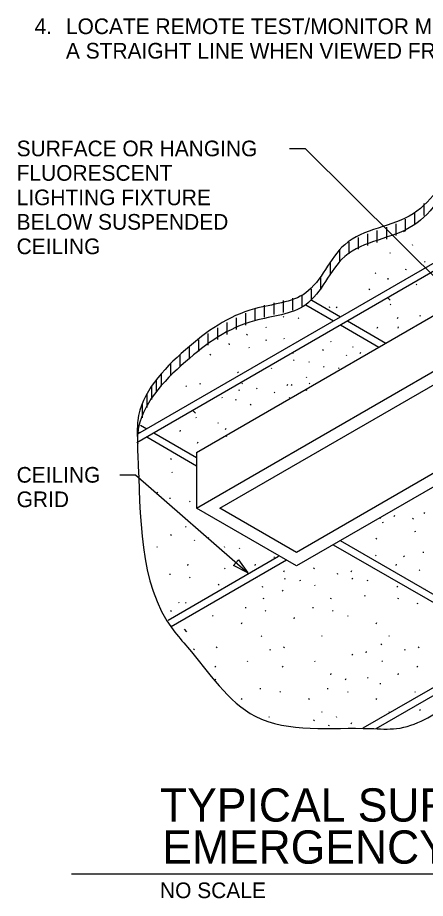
# Model space of a CAD drawing. Extents: x -12092.5 to -12048.3, y -12283.2 to -12205.8.
# Drawn here: x -12092.51 to -12075.14, y -12281.89 to -12244.4 of the extents above; entities that cross this region are included whole.
import ezdxf

# ---------------------------------------------------------------- set-up
doc = ezdxf.new("R2010")
doc.units = 0
for name, color, linetype in [('G-ANNO-TEXT', 7, 'Continuous'), ('G-DETL-LINE', 7, 'Continuous'), ('G-DETL-OTLN', 7, 'Continuous'), ('G-DETL-PATT', 7, 'Continuous')]:
    doc.layers.add(name, color=color, linetype=linetype)

msp = doc.modelspace()

# ---------------------------------------------------------------- linework, layer by layer
at = {"layer": 'G-ANNO-TEXT'}
for p, q in [((-12080.926, -12249.965), (-12080.259, -12249.965)), ((-12080.259, -12249.965), (-12073.795, -12256.39)), ((-12088.159, -12263.859), (-12087.492, -12263.859)), ((-12087.492, -12263.859), (-12082.703, -12268.036)), ((-12090.219, -12280.845), (-12051.694, -12280.845))]:
    msp.add_line(p, q, dxfattribs=at)
msp.add_lwpolyline([(-12083.096, -12267.472), (-12082.703, -12268.036), (-12083.315, -12267.724)], close=True, dxfattribs=at)
at = {"layer": 'G-DETL-LINE'}
for p, q in [((-12064.841, -12249.447), (-12087.432, -12262.49)), ((-12065.21, -12249.313), (-12087.407, -12262.129)), ((-12079.973, -12256.43), (-12078.755, -12257.133)), ((-12080.234, -12256.626), (-12079.055, -12257.307)), ((-12078.455, -12257.307), (-12076.824, -12258.249)), ((-12078.755, -12257.48), (-12077.124, -12258.422)), ((-12054.535, -12261.21), (-12077.813, -12274.649)), ((-12087.272, -12261.748), (-12087.01, -12261.899)), ((-12054.64, -12261.617), (-12077.25, -12274.671)), ((-12087.378, -12262.033), (-12087.31, -12262.072)), ((-12086.71, -12262.072), (-12084.891, -12263.122)), ((-12087.01, -12262.246), (-12084.891, -12263.469)), ((-12078.766, -12266.658), (-12071.369, -12270.929)), ((-12079.067, -12266.832), (-12071.669, -12271.102)), ((-12086.103, -12270.04), (-12081.401, -12267.326)), ((-12081.057, -12267.493), (-12085.964, -12270.325))]:
    msp.add_line(p, q, dxfattribs=at)
for points in [[(-12065.21, -12248.806), (-12068.289, -12248.263), (-12071.882, -12249.46), (-12073.511, -12250.469), (-12075.66, -12252.742), (-12078.578, -12254.061), (-12080.241, -12256.115), (-12082.417, -12256.792), (-12085.365, -12258.54), (-12087.392, -12261.547), (-12087.416, -12262.222)], [(-12065.21, -12249.313), (-12068.289, -12248.77), (-12071.882, -12249.967), (-12073.511, -12250.976), (-12075.66, -12253.249), (-12078.578, -12254.568), (-12080.241, -12256.622), (-12082.417, -12257.299), (-12085.365, -12259.047), (-12087.392, -12262.054), (-12087.392, -12263.005), (-12085.887, -12270.459), (-12085.273, -12271.196), (-12082.387, -12274.137), (-12077.474, -12274.659), (-12076.368, -12274.659), (-12074.064, -12273.585), (-12070.747, -12271.315), (-12067.093, -12270.272), (-12063.192, -12269.382), (-12061.824, -12266.02), (-12056.45, -12263.782), (-12054.538, -12261.235), (-12060.102, -12255.74), (-12060.918, -12251.902), (-12062.515, -12250.552), (-12064.841, -12249.447), (-12065.182, -12249.321)]]:
    msp.add_spline(points, degree=3, dxfattribs=at)
at = {"layer": 'G-DETL-OTLN'}
for p, q in [((-12084.891, -12262.907), (-12068.869, -12253.656)), ((-12084.891, -12265.279), (-12068.869, -12256.029)), ((-12083.891, -12265.279), (-12068.869, -12256.606)), ((-12064.612, -12258.486), (-12080.634, -12267.737)), ((-12065.612, -12258.486), (-12080.634, -12267.159)), ((-12084.891, -12262.907), (-12084.891, -12265.279)), ((-12080.634, -12267.737), (-12084.891, -12265.279)), ((-12080.634, -12267.159), (-12083.891, -12265.279))]:
    msp.add_line(p, q, dxfattribs=at)
at = {"layer": 'G-DETL-PATT'}
for p, q in [((-12075.203, -12252.314), (-12075.203, -12252.821)), ((-12075.603, -12252.695), (-12075.603, -12253.203)), ((-12076.403, -12253.168), (-12076.403, -12253.675)), ((-12076.003, -12252.973), (-12076.003, -12253.48)), ((-12077.203, -12253.457), (-12077.203, -12253.964)), ((-12076.803, -12253.321), (-12076.803, -12253.828)), ((-12076.069, -12253.475), (-12076.047, -12253.508)), ((-12078.403, -12253.949), (-12078.403, -12254.456)), ((-12078.003, -12253.749), (-12078.003, -12254.256)), ((-12077.603, -12253.593), (-12077.603, -12254.1)), ((-12078.803, -12254.256), (-12078.803, -12254.763)), ((-12075.707, -12254.05), (-12075.685, -12254.082)), ((-12076.661, -12254.391), (-12076.639, -12254.423)), ((-12079.203, -12254.805), (-12079.203, -12255.313)), ((-12075.175, -12254.774), (-12075.153, -12254.806)), ((-12077.278, -12255.253), (-12077.257, -12255.285)), ((-12075.977, -12255.136), (-12075.955, -12255.088)), ((-12079.603, -12255.474), (-12079.603, -12255.981)), ((-12076.744, -12255.493), (-12076.739, -12255.541)), ((-12075.53, -12255.736), (-12075.508, -12255.768)), ((-12080.403, -12256.195), (-12080.403, -12256.702)), ((-12080.003, -12255.949), (-12080.003, -12256.456)), ((-12077.536, -12255.983), (-12077.514, -12255.935)), ((-12081.603, -12256.531), (-12081.603, -12257.038)), ((-12081.203, -12256.441), (-12081.203, -12256.948)), ((-12080.803, -12256.339), (-12080.803, -12256.846)), ((-12076.741, -12256.324), (-12076.646, -12256.426)), ((-12082.403, -12256.785), (-12082.403, -12257.292)), ((-12082.003, -12256.636), (-12082.003, -12257.143)), ((-12079.246, -12256.698), (-12079.224, -12256.731)), ((-12078.938, -12256.711), (-12078.917, -12256.743)), ((-12076.637, -12256.587), (-12076.616, -12256.619)), ((-12083.203, -12257.169), (-12083.203, -12257.676)), ((-12082.803, -12256.974), (-12082.803, -12257.481)), ((-12081.197, -12257.114), (-12081.176, -12257.146)), ((-12080.56, -12257.172), (-12080.538, -12257.205)), ((-12076.326, -12257.198), (-12076.304, -12257.15)), ((-12075.364, -12257.111), (-12075.343, -12257.062)), ((-12084.003, -12257.596), (-12084.003, -12258.103)), ((-12083.603, -12257.375), (-12083.603, -12257.882)), ((-12081.943, -12257.556), (-12081.922, -12257.588)), ((-12077.189, -12257.61), (-12077.167, -12257.562)), ((-12076.308, -12257.61), (-12076.286, -12257.562)), ((-12084.403, -12257.837), (-12084.403, -12258.345)), ((-12082.746, -12257.918), (-12082.724, -12257.869)), ((-12081.177, -12258.035), (-12081.156, -12258.067)), ((-12085.203, -12258.407), (-12085.203, -12258.914)), ((-12084.803, -12258.106), (-12084.803, -12258.613)), ((-12083.513, -12258.275), (-12083.507, -12258.323)), ((-12082.667, -12258.418), (-12082.646, -12258.45)), ((-12081.926, -12258.139), (-12081.904, -12258.091)), ((-12079.187, -12258.165), (-12079.165, -12258.198)), ((-12078.25, -12258.389), (-12078.229, -12258.422)), ((-12085.603, -12258.746), (-12085.603, -12259.254)), ((-12084.305, -12258.765), (-12084.283, -12258.716)), ((-12080.784, -12258.689), (-12080.762, -12258.641)), ((-12079.505, -12258.565), (-12079.484, -12258.517)), ((-12078.518, -12258.752), (-12078.496, -12258.785)), ((-12077.914, -12258.689), (-12077.892, -12258.641)), ((-12086.003, -12259.12), (-12086.003, -12259.639)), ((-12080.758, -12258.964), (-12080.736, -12258.996)), ((-12080.11, -12259.034), (-12080.088, -12259.067)), ((-12086.403, -12259.551), (-12086.403, -12260.089)), ((-12083.145, -12259.48), (-12083.123, -12259.513)), ((-12081.712, -12259.305), (-12081.691, -12259.337)), ((-12079.48, -12259.246), (-12079.458, -12259.279)), ((-12078.842, -12259.305), (-12078.821, -12259.337)), ((-12086.603, -12259.798), (-12086.603, -12260.35)), ((-12083.446, -12259.841), (-12083.441, -12259.832)), ((-12080.226, -12259.688), (-12080.204, -12259.72)), ((-12086.803, -12260.079), (-12086.803, -12260.646)), ((-12085.345, -12260.067), (-12085.324, -12260.1)), ((-12084.742, -12260.004), (-12084.72, -12259.956)), ((-12083.078, -12260.271), (-12083.056, -12260.223)), ((-12082.959, -12259.955), (-12082.938, -12259.987)), ((-12082.329, -12260.167), (-12082.308, -12260.199)), ((-12081.028, -12260.05), (-12081.007, -12260.001)), ((-12080.838, -12260.06), (-12080.816, -12260.011)), ((-12080.208, -12260.271), (-12080.187, -12260.223)), ((-12080.089, -12259.955), (-12080.068, -12259.987)), ((-12087.003, -12260.411), (-12087.003, -12260.995)), ((-12083.819, -12260.55), (-12083.798, -12260.582)), ((-12083.217, -12260.685), (-12083.195, -12260.637)), ((-12081.579, -12260.338), (-12081.558, -12260.37)), ((-12080.95, -12260.55), (-12080.928, -12260.582)), ((-12087.203, -12260.841), (-12087.203, -12261.435)), ((-12082.587, -12260.897), (-12082.565, -12260.848)), ((-12085.03, -12261.138), (-12084.935, -12261.239)), ((-12084.927, -12261.401), (-12084.905, -12261.433)), ((-12087.403, -12261.626), (-12087.403, -12262.106)), ((-12083.99, -12261.625), (-12083.968, -12261.657)), ((-12085.588, -12262.012), (-12085.567, -12261.964)), ((-12083.654, -12261.925), (-12083.632, -12261.876)), ((-12083.628, -12262.199), (-12083.606, -12262.232)), ((-12087.39, -12262.517), (-12087.389, -12262.529)), ((-12084.845, -12262.507), (-12084.823, -12262.458)), ((-12085.982, -12263.206), (-12085.96, -12263.158)), ((-12085.948, -12263.734), (-12085.927, -12263.766)), ((-12086.566, -12264.596), (-12086.544, -12264.629)), ((-12086.032, -12264.836), (-12086.026, -12264.885)), ((-12085.186, -12264.979), (-12085.164, -12265.012)), ((-12075.193, -12265.504), (-12075.171, -12265.456)), ((-12077.075, -12265.692), (-12077.053, -12265.724)), ((-12076.975, -12265.866), (-12076.954, -12265.899)), ((-12076.471, -12265.629), (-12076.45, -12265.58)), ((-12075.674, -12265.75), (-12075.652, -12265.701)), ((-12085.356, -12266.054), (-12085.334, -12266.087)), ((-12075.596, -12266.249), (-12075.574, -12266.282)), ((-12085.982, -12266.442), (-12085.96, -12266.393)), ((-12084.994, -12266.629), (-12084.973, -12266.661)), ((-12084.39, -12266.566), (-12084.369, -12266.517)), ((-12077.233, -12266.597), (-12077.211, -12266.548)), ((-12086.586, -12266.911), (-12086.564, -12266.943)), ((-12083.716, -12266.911), (-12083.694, -12266.943)), ((-12083.078, -12266.969), (-12083.057, -12267.002)), ((-12081.592, -12267.353), (-12081.571, -12267.385)), ((-12077.267, -12267.277), (-12077.245, -12267.31)), ((-12076.073, -12267.312), (-12076.051, -12267.344)), ((-12075.242, -12267.134), (-12075.237, -12267.183)), ((-12085.264, -12267.715), (-12085.243, -12267.666)), ((-12082.394, -12267.715), (-12082.373, -12267.666)), ((-12079.891, -12267.863), (-12079.869, -12267.814)), ((-12076.391, -12267.712), (-12076.37, -12267.663)), ((-12086.032, -12268.072), (-12086.026, -12268.12)), ((-12083.696, -12267.832), (-12083.674, -12267.864)), ((-12081.169, -12267.987), (-12081.148, -12267.938)), ((-12078.903, -12268.05), (-12078.882, -12268.082)), ((-12078.3, -12267.987), (-12078.278, -12267.938)), ((-12075.404, -12267.899), (-12075.382, -12267.931)), ((-12085.186, -12268.215), (-12085.164, -12268.247)), ((-12083.953, -12268.562), (-12083.932, -12268.513)), ((-12082.316, -12268.215), (-12082.314, -12268.218)), ((-12081.144, -12268.262), (-12081.122, -12268.294)), ((-12080.495, -12268.332), (-12080.474, -12268.365)), ((-12079.865, -12268.544), (-12079.844, -12268.576)), ((-12078.274, -12268.262), (-12078.252, -12268.294)), ((-12077.625, -12268.332), (-12077.604, -12268.365)), ((-12082.098, -12268.602), (-12082.076, -12268.635)), ((-12081.241, -12268.774), (-12081.219, -12268.806)), ((-12076.358, -12268.602), (-12076.336, -12268.635)), ((-12075.186, -12268.726), (-12075.171, -12268.691)), ((-12085.663, -12269.277), (-12085.642, -12269.31)), ((-12085.356, -12269.29), (-12085.334, -12269.322)), ((-12082.043, -12269.136), (-12082.022, -12269.088)), ((-12079.174, -12269.136), (-12079.152, -12269.088)), ((-12077.742, -12268.986), (-12077.72, -12269.018)), ((-12076.304, -12269.136), (-12076.282, -12269.088)), ((-12075.484, -12269.357), (-12075.462, -12269.309)), ((-12085.982, -12269.677), (-12085.96, -12269.629)), ((-12082.811, -12269.493), (-12082.805, -12269.541)), ((-12081.965, -12269.636), (-12081.943, -12269.668)), ((-12079.941, -12269.493), (-12079.935, -12269.541)), ((-12079.095, -12269.636), (-12079.073, -12269.668)), ((-12084.205, -12269.848), (-12084.183, -12269.88)), ((-12080.732, -12269.983), (-12080.711, -12269.935)), ((-12078.465, -12269.848), (-12078.444, -12269.88)), ((-12085.416, -12270.436), (-12085.321, -12270.537)), ((-12082.973, -12270.195), (-12082.951, -12270.146)), ((-12077.233, -12270.195), (-12077.211, -12270.146)), ((-12082.135, -12270.711), (-12082.114, -12270.743)), ((-12079.573, -12270.698), (-12079.551, -12270.731)), ((-12076.703, -12270.698), (-12076.681, -12270.731)), ((-12084.039, -12271.222), (-12084.018, -12271.174)), ((-12081.169, -12271.222), (-12081.148, -12271.174)), ((-12077.021, -12271.098), (-12076.999, -12271.05)), ((-12075.43, -12271.222), (-12075.408, -12271.174)), ((-12085.001, -12271.31), (-12084.979, -12271.261)), ((-12081.773, -12271.285), (-12081.752, -12271.318)), ((-12078.274, -12271.497), (-12078.252, -12271.53)), ((-12077.67, -12271.434), (-12077.648, -12271.386)), ((-12076.034, -12271.285), (-12076.012, -12271.318)), ((-12082.735, -12271.779), (-12082.714, -12271.812)), ((-12079.865, -12271.779), (-12079.844, -12271.812)), ((-12076.996, -12271.779), (-12076.974, -12271.812)), ((-12084.111, -12272.009), (-12084.089, -12272.042)), ((-12081.241, -12272.009), (-12081.219, -12272.042)), ((-12079.174, -12272.371), (-12079.152, -12272.323)), ((-12076.304, -12272.371), (-12076.282, -12272.323)), ((-12075.501, -12272.009), (-12075.48, -12272.042)), ((-12084.093, -12272.593), (-12084.072, -12272.544)), ((-12078.544, -12272.583), (-12078.522, -12272.535)), ((-12077.605, -12272.488), (-12077.583, -12272.52)), ((-12082.181, -12272.94), (-12082.175, -12272.988)), ((-12079.311, -12272.94), (-12079.306, -12272.988)), ((-12077.071, -12272.728), (-12077.066, -12272.777)), ((-12082.973, -12273.43), (-12082.951, -12273.382)), ((-12081.335, -12273.083), (-12081.314, -12273.115)), ((-12080.103, -12273.43), (-12080.081, -12273.382)), ((-12078.465, -12273.083), (-12078.444, -12273.115)), ((-12077.233, -12273.43), (-12077.211, -12273.382)), ((-12075.596, -12273.083), (-12075.574, -12273.115)), ((-12081.813, -12274.145), (-12081.791, -12274.178)), ((-12079.573, -12273.934), (-12079.551, -12273.966)), ((-12078.943, -12274.145), (-12078.921, -12274.178)), ((-12076.703, -12273.934), (-12076.681, -12273.966)), ((-12075.39, -12273.855), (-12075.369, -12273.888)), ((-12079.891, -12274.334), (-12079.869, -12274.285)), ((-12079.261, -12274.545), (-12079.24, -12274.497)), ((-12078.3, -12274.458), (-12078.278, -12274.409))]:
    msp.add_line(p, q, dxfattribs=at)

# ---------------------------------------------------------------- texts
at = {"layer": 'G-ANNO-TEXT'}
for s, height, p in [('4.', 0.6667, (-12091.788, -12245.097)), ('LOCATE REMOTE TEST/MONITOR MODULES IDENTICALLY SO THAT THEY FORM', 0.66667, (-12090.453, -12245.097)), ('A STRAIGHT LINE WHEN VIEWED FROM END OF CORRIDOR OR ROOM.', 0.66667, (-12090.453, -12246.139)), ('SURFACE OR HANGING', 0.66667, (-12092.553, -12250.298)), ('FLUORESCENT', 0.66667, (-12092.553, -12251.34)), ('LIGHTING FIXTURE', 0.66667, (-12092.553, -12252.381)), ('BELOW SUSPENDED', 0.66667, (-12092.553, -12253.423)), ('CEILING', 0.6667, (-12092.553, -12254.465)), ('CEILING', 0.6667, (-12092.553, -12264.192)), ('GRID', 0.6667, (-12092.553, -12265.234)), ('TYPICAL SURFACE OR HANGING', 1.41667, (-12086.446, -12278.621)), ('EMERGENCY LIGHTING FIXTURE', 1.41667, (-12086.352, -12280.413)), ('NO SCALE', 0.6667, (-12086.446, -12281.88))]:
    msp.add_text(s, height=height, dxfattribs=at).set_placement(p)

doc.saveas('drawing.dxf')
